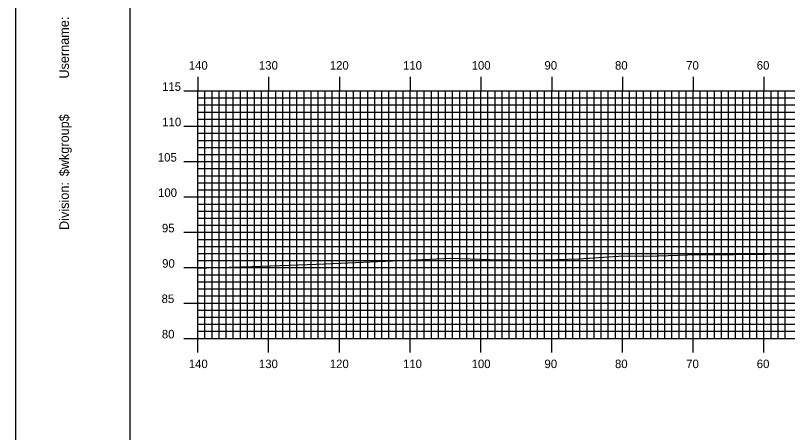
# Model space of a CAD drawing. Extents: x 1760610 to 1760954, y 442591 to 442811.
# Drawn here: x 1760610.4 to 1760719.5, y 442650.4 to 442709.3 of the extents above; entities that cross this region are included whole.
import ezdxf

# ---------------------------------------------------------------- set-up
doc = ezdxf.new("R2010")
doc.units = 0
for name, color, linetype in [('BORDER', 7, 'Continuous'), ('H_V ANNOTATION', 7, 'Continuous'), ('MAJOR', 7, 'Continuous'), ('MINOR', 7, 'Continuous'), ('PLOT BOUNDARY', 7, 'Continuous'), ('S_Roadway_Centerline', 7, 'Continuous')]:
    doc.layers.add(name, color=color, linetype=linetype)

msp = doc.modelspace()

# ---------------------------------------------------------------- linework, layer by layer
at = {"layer": 'BORDER'}
msp.add_lwpolyline([(1760626.61, 442596.67), (1760946.61, 442596.67), (1760946.61, 442806.67), (1760626.61, 442806.67)], close=True, dxfattribs=at)
at = {"layer": 'MAJOR'}
for p, q in [((1760636.21, 442700.67), (1760636.21, 442698.67)), ((1760646.21, 442700.67), (1760646.21, 442698.67)), ((1760656.21, 442700.67), (1760656.21, 442698.67)), ((1760666.21, 442700.67), (1760666.21, 442698.67)), ((1760676.21, 442700.67), (1760676.21, 442698.67)), ((1760686.21, 442700.67), (1760686.21, 442698.67)), ((1760696.21, 442700.67), (1760696.21, 442698.67)), ((1760706.21, 442700.67), (1760706.21, 442698.67)), ((1760716.21, 442700.67), (1760716.21, 442698.67)), ((1760634.21, 442698.67), (1760636.21, 442698.67)), ((1760636.21, 442698.67), (1760916.21, 442698.67)), ((1760636.21, 442663.67), (1760636.21, 442698.67)), ((1760636.21, 442663.67), (1760636.21, 442698.67)), ((1760636.21, 442698.67), (1760916.21, 442698.67)), ((1760646.21, 442663.67), (1760646.21, 442698.67)), ((1760656.21, 442663.67), (1760656.21, 442698.67)), ((1760666.21, 442663.67), (1760666.21, 442698.67)), ((1760676.21, 442663.67), (1760676.21, 442698.67)), ((1760686.21, 442663.67), (1760686.21, 442698.67)), ((1760696.21, 442663.67), (1760696.21, 442698.67)), ((1760706.21, 442663.67), (1760706.21, 442698.67)), ((1760716.21, 442663.67), (1760716.21, 442698.67)), ((1760634.21, 442693.67), (1760636.21, 442693.67)), ((1760636.21, 442693.67), (1760916.21, 442693.67)), ((1760634.21, 442688.67), (1760636.21, 442688.67)), ((1760636.21, 442688.67), (1760916.21, 442688.67)), ((1760634.21, 442683.67), (1760636.21, 442683.67)), ((1760636.21, 442683.67), (1760916.21, 442683.67)), ((1760634.21, 442678.67), (1760636.21, 442678.67)), ((1760636.21, 442678.67), (1760916.21, 442678.67)), ((1760634.21, 442673.67), (1760636.21, 442673.67)), ((1760636.21, 442673.67), (1760916.21, 442673.67)), ((1760634.21, 442668.67), (1760636.21, 442668.67)), ((1760636.21, 442668.67), (1760916.21, 442668.67)), ((1760634.21, 442663.67), (1760636.21, 442663.67)), ((1760636.21, 442663.67), (1760916.21, 442663.67)), ((1760636.21, 442663.67), (1760916.21, 442663.67)), ((1760636.21, 442661.66), (1760636.21, 442663.67)), ((1760646.21, 442661.66), (1760646.21, 442663.67)), ((1760656.21, 442661.66), (1760656.21, 442663.67)), ((1760666.21, 442661.66), (1760666.21, 442663.67)), ((1760676.21, 442661.66), (1760676.21, 442663.67)), ((1760686.21, 442661.66), (1760686.21, 442663.67)), ((1760696.21, 442661.66), (1760696.21, 442663.67)), ((1760706.21, 442661.66), (1760706.21, 442663.67)), ((1760716.21, 442661.66), (1760716.21, 442663.67))]:
    msp.add_line(p, q, dxfattribs=at)
at = {"layer": 'MINOR'}
for p, q in [((1760637.21, 442663.67), (1760637.21, 442698.67)), ((1760638.21, 442663.67), (1760638.21, 442698.67)), ((1760639.21, 442663.67), (1760639.21, 442698.67)), ((1760640.21, 442663.67), (1760640.21, 442698.67)), ((1760641.21, 442663.67), (1760641.21, 442698.67)), ((1760642.21, 442663.67), (1760642.21, 442698.67)), ((1760643.21, 442663.67), (1760643.21, 442698.67)), ((1760644.21, 442663.67), (1760644.21, 442698.67)), ((1760645.21, 442663.67), (1760645.21, 442698.67)), ((1760647.21, 442663.67), (1760647.21, 442698.67)), ((1760648.21, 442663.67), (1760648.21, 442698.67)), ((1760649.21, 442663.67), (1760649.21, 442698.67)), ((1760650.21, 442663.67), (1760650.21, 442698.67)), ((1760651.21, 442663.67), (1760651.21, 442698.67)), ((1760652.21, 442663.67), (1760652.21, 442698.67)), ((1760653.21, 442663.67), (1760653.21, 442698.67)), ((1760654.21, 442663.67), (1760654.21, 442698.67)), ((1760655.21, 442663.67), (1760655.21, 442698.67)), ((1760657.21, 442663.67), (1760657.21, 442698.67)), ((1760658.21, 442663.67), (1760658.21, 442698.67)), ((1760659.21, 442663.67), (1760659.21, 442698.67)), ((1760660.21, 442663.67), (1760660.21, 442698.67)), ((1760661.21, 442663.67), (1760661.21, 442698.67)), ((1760662.21, 442663.67), (1760662.21, 442698.67)), ((1760663.21, 442663.67), (1760663.21, 442698.67)), ((1760664.21, 442663.67), (1760664.21, 442698.67)), ((1760665.21, 442663.67), (1760665.21, 442698.67)), ((1760667.21, 442663.67), (1760667.21, 442698.67)), ((1760668.21, 442663.67), (1760668.21, 442698.67)), ((1760669.21, 442663.67), (1760669.21, 442698.67)), ((1760670.21, 442663.67), (1760670.21, 442698.67)), ((1760671.21, 442663.67), (1760671.21, 442698.67)), ((1760672.21, 442663.67), (1760672.21, 442698.67)), ((1760673.21, 442663.67), (1760673.21, 442698.67)), ((1760674.21, 442663.67), (1760674.21, 442698.67)), ((1760675.21, 442663.67), (1760675.21, 442698.67)), ((1760677.21, 442663.67), (1760677.21, 442698.67)), ((1760678.21, 442663.67), (1760678.21, 442698.67)), ((1760679.21, 442663.67), (1760679.21, 442698.67)), ((1760680.21, 442663.67), (1760680.21, 442698.67)), ((1760681.21, 442663.67), (1760681.21, 442698.67)), ((1760682.21, 442663.67), (1760682.21, 442698.67)), ((1760683.21, 442663.67), (1760683.21, 442698.67)), ((1760684.21, 442663.67), (1760684.21, 442698.67)), ((1760685.21, 442663.67), (1760685.21, 442698.67)), ((1760687.21, 442663.67), (1760687.21, 442698.67)), ((1760688.21, 442663.67), (1760688.21, 442698.67)), ((1760689.21, 442663.67), (1760689.21, 442698.67)), ((1760690.21, 442663.67), (1760690.21, 442698.67)), ((1760691.21, 442663.67), (1760691.21, 442698.67)), ((1760692.21, 442663.67), (1760692.21, 442698.67)), ((1760693.21, 442663.67), (1760693.21, 442698.67)), ((1760694.21, 442663.67), (1760694.21, 442698.67)), ((1760695.21, 442663.67), (1760695.21, 442698.67)), ((1760697.21, 442663.67), (1760697.21, 442698.67)), ((1760698.21, 442663.67), (1760698.21, 442698.67)), ((1760699.21, 442663.67), (1760699.21, 442698.67)), ((1760700.21, 442663.67), (1760700.21, 442698.67)), ((1760701.21, 442663.67), (1760701.21, 442698.67)), ((1760702.21, 442663.67), (1760702.21, 442698.67)), ((1760703.21, 442663.67), (1760703.21, 442698.67)), ((1760704.21, 442663.67), (1760704.21, 442698.67)), ((1760705.21, 442663.67), (1760705.21, 442698.67)), ((1760707.21, 442663.67), (1760707.21, 442698.67)), ((1760708.21, 442663.67), (1760708.21, 442698.67)), ((1760709.21, 442663.67), (1760709.21, 442698.67)), ((1760710.21, 442663.67), (1760710.21, 442698.67)), ((1760711.21, 442663.67), (1760711.21, 442698.67)), ((1760712.21, 442663.67), (1760712.21, 442698.67)), ((1760713.21, 442663.67), (1760713.21, 442698.67)), ((1760714.21, 442663.67), (1760714.21, 442698.67)), ((1760715.21, 442663.67), (1760715.21, 442698.67)), ((1760717.21, 442663.67), (1760717.21, 442698.67)), ((1760718.21, 442663.67), (1760718.21, 442698.67)), ((1760719.21, 442663.67), (1760719.21, 442698.67)), ((1760636.21, 442697.67), (1760916.21, 442697.67)), ((1760636.21, 442697.67), (1760638.22, 442697.67)), ((1760636.21, 442696.67), (1760916.21, 442696.67)), ((1760636.21, 442696.67), (1760638.22, 442696.67)), ((1760636.21, 442695.67), (1760916.21, 442695.67)), ((1760636.21, 442695.67), (1760638.22, 442695.67)), ((1760636.21, 442694.67), (1760916.21, 442694.67)), ((1760636.21, 442694.67), (1760638.22, 442694.67)), ((1760636.21, 442692.67), (1760916.21, 442692.67)), ((1760636.21, 442692.67), (1760638.22, 442692.67)), ((1760636.21, 442691.67), (1760916.21, 442691.67)), ((1760636.21, 442691.67), (1760638.22, 442691.67)), ((1760636.21, 442690.67), (1760916.21, 442690.67)), ((1760636.21, 442690.67), (1760638.22, 442690.67)), ((1760636.21, 442689.67), (1760916.21, 442689.67)), ((1760636.21, 442689.67), (1760638.22, 442689.67)), ((1760636.21, 442687.67), (1760916.21, 442687.67)), ((1760636.21, 442687.67), (1760638.22, 442687.67)), ((1760636.21, 442686.67), (1760916.21, 442686.67)), ((1760636.21, 442686.67), (1760638.22, 442686.67)), ((1760636.21, 442685.67), (1760916.21, 442685.67)), ((1760636.21, 442685.67), (1760638.22, 442685.67)), ((1760636.21, 442684.67), (1760916.21, 442684.67)), ((1760636.21, 442684.67), (1760638.22, 442684.67)), ((1760636.21, 442682.67), (1760916.21, 442682.67)), ((1760636.21, 442682.67), (1760638.22, 442682.67)), ((1760636.21, 442681.67), (1760916.21, 442681.67)), ((1760636.21, 442681.67), (1760638.22, 442681.67)), ((1760636.21, 442680.67), (1760916.21, 442680.67)), ((1760636.21, 442680.67), (1760638.22, 442680.67)), ((1760636.21, 442679.67), (1760916.21, 442679.67)), ((1760636.21, 442679.67), (1760638.22, 442679.67)), ((1760636.21, 442677.67), (1760916.21, 442677.67)), ((1760636.21, 442677.67), (1760638.22, 442677.67)), ((1760636.21, 442676.67), (1760916.21, 442676.67)), ((1760636.21, 442676.67), (1760638.22, 442676.67)), ((1760636.21, 442675.67), (1760916.21, 442675.67)), ((1760636.21, 442675.67), (1760638.22, 442675.67)), ((1760636.21, 442674.67), (1760916.21, 442674.67)), ((1760636.21, 442674.67), (1760638.22, 442674.67)), ((1760636.21, 442672.67), (1760916.21, 442672.67)), ((1760636.21, 442672.67), (1760638.22, 442672.67)), ((1760636.21, 442671.67), (1760916.21, 442671.67)), ((1760636.21, 442671.67), (1760638.22, 442671.67)), ((1760636.21, 442670.67), (1760916.21, 442670.67)), ((1760636.21, 442670.67), (1760638.22, 442670.67)), ((1760636.21, 442669.67), (1760916.21, 442669.67)), ((1760636.21, 442669.67), (1760638.22, 442669.67)), ((1760636.21, 442667.67), (1760916.21, 442667.67)), ((1760636.21, 442667.67), (1760638.22, 442667.67)), ((1760636.21, 442666.67), (1760916.21, 442666.67)), ((1760636.21, 442666.67), (1760638.22, 442666.67)), ((1760636.21, 442665.67), (1760916.21, 442665.67)), ((1760636.21, 442665.67), (1760638.22, 442665.67)), ((1760636.21, 442664.67), (1760916.21, 442664.67)), ((1760636.21, 442664.67), (1760638.22, 442664.67))]:
    msp.add_line(p, q, dxfattribs=at)
at = {"layer": 'PLOT BOUNDARY'}
msp.add_lwpolyline([(1760610.43, 442590.55), (1760950.43, 442590.55), (1760950.43, 442810.55), (1760610.43, 442810.55)], close=True, dxfattribs=at)
at = {"layer": 'S_Roadway_Centerline'}
msp.add_lwpolyline([(1760636.21, 442673.66), (1760637.49, 442673.66), (1760643.83, 442673.84), (1760654.25, 442674.21), (1760666.91, 442674.8), (1760671.97, 442675), (1760677.42, 442674.83), (1760683.81, 442674.74), (1760690.06, 442674.93), (1760695.64, 442675.28), (1760701.32, 442675.33), (1760706.83, 442675.53), (1760711.92, 442675.53), (1760730.31, 442675.71)], dxfattribs=at)

# ---------------------------------------------------------------- texts
at = {"layer": 'BORDER'}
for s, p in [('Username:', (1760617.98, 442700.4)), ('$wkgroup$', (1760617.98, 442686.6)), ('Division:', (1760617.98, 442679))]:
    msp.add_text(s, height=1.339, rotation=90, dxfattribs=at).set_placement(p)
at = {"layer": 'H_V ANNOTATION'}
for s, p in [('140', (1760634.92, 442701.67)), ('130', (1760644.84, 442701.67)), ('120', (1760654.85, 442701.67)), ('110', (1760665.2, 442701.67)), ('100', (1760674.9, 442701.67)), ('90', (1760685.19, 442701.67)), ('80', (1760695.16, 442701.67)), ('70', (1760705.22, 442701.67)), ('60', (1760715.19, 442701.67)), ('115', (1760631.15, 442698.67)), ('110', (1760631.18, 442693.67)), ('105', (1760630.55, 442688.67)), ('100', (1760630.58, 442683.67)), ('95', (1760631.13, 442678.67)), ('90', (1760631.16, 442673.67)), ('85', (1760631.08, 442668.67)), ('80', (1760631.12, 442663.67)), ('140', (1760634.92, 442659.47)), ('130', (1760644.84, 442659.47)), ('120', (1760654.85, 442659.47)), ('110', (1760665.2, 442659.47)), ('100', (1760674.9, 442659.47)), ('90', (1760685.19, 442659.47)), ('80', (1760695.16, 442659.47)), ('70', (1760705.22, 442659.47)), ('60', (1760715.19, 442659.47))]:
    msp.add_text(s, height=1.2, dxfattribs=at).set_placement(p)
at = {"layer": 'MAJOR'}
msp.add_text('-', height=0.012, dxfattribs=at).set_placement((1760636.2, 442663.67))

doc.saveas('drawing.dxf')
